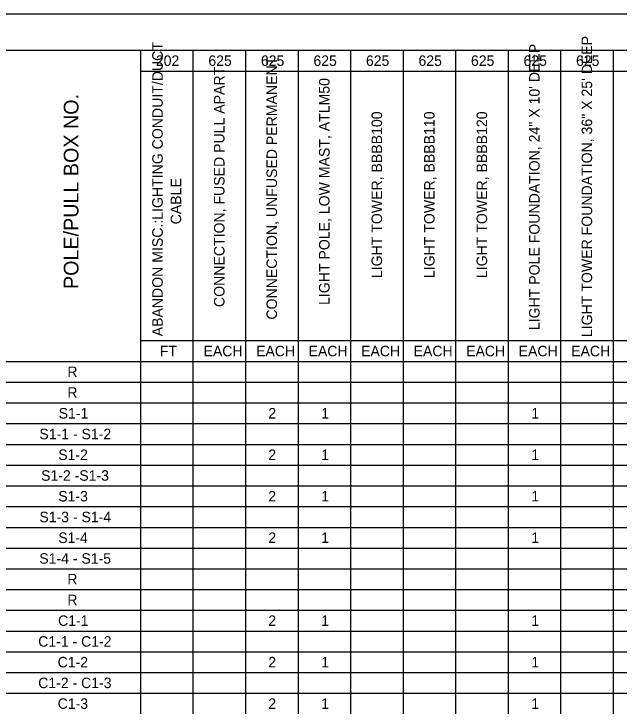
# Model space of a CAD drawing. Extents: x -1022.2 to -988.2, y -965.8 to -943.8.
# Drawn here: x -1013.68 to -1005.35, y -953.43 to -943.79 of the extents above; entities that cross this region are included whole.
import ezdxf

# ---------------------------------------------------------------- set-up
doc = ezdxf.new("R2010")
doc.units = 0
for name, color, linetype in [('Default', 7, 'Continuous'), ('SH_Border', 7, 'Continuous'), ('SH_Cut_Line', 7, 'Continuous')]:
    doc.layers.add(name, color=color, linetype=linetype)

msp = doc.modelspace()

# ---------------------------------------------------------------- linework, layer by layer
at = {"layer": 'Default'}
for p, q in [((-1016.8167, -944.2862), (-1009.047, -944.2862)), ((-1011.9419, -944.2862), (-1011.9419, -944.5719)), ((-1011.2181, -944.2862), (-1011.2181, -944.5719)), ((-1010.4944, -944.2862), (-1010.4944, -944.5719)), ((-1009.7707, -944.2862), (-1009.7707, -944.5719)), ((-1009.047, -944.2862), (-1008.3233, -944.2862)), ((-1009.047, -944.2862), (-1009.047, -944.5719)), ((-1008.3233, -944.2862), (-1007.5995, -944.2862)), ((-1008.3233, -944.2862), (-1008.3233, -944.5719)), ((-1007.5995, -944.2862), (-1006.8758, -944.2862)), ((-1007.5995, -944.2862), (-1007.5995, -944.5719)), ((-1006.8758, -944.2862), (-1005.4284, -944.2862)), ((-1006.8758, -944.2862), (-1006.8758, -944.5719)), ((-1006.1521, -944.2862), (-1006.1521, -944.5719)), ((-1005.4284, -944.2862), (-998.9149, -944.2862)), ((-1005.4284, -944.2862), (-1005.4284, -944.5719)), ((-1011.9419, -944.5719), (-1009.047, -944.5719)), ((-1011.9419, -944.5719), (-1011.9419, -944.8577)), ((-1011.2181, -944.5719), (-1011.2181, -944.8577)), ((-1010.4944, -944.5719), (-1010.4944, -944.8577)), ((-1009.7707, -944.5719), (-1009.7707, -944.8577)), ((-1009.047, -944.5719), (-1008.3233, -944.5719)), ((-1009.047, -944.5719), (-1009.047, -944.8577)), ((-1008.3233, -944.5719), (-1007.5995, -944.5719)), ((-1008.3233, -944.5719), (-1008.3233, -944.8577)), ((-1007.5995, -944.5719), (-1006.8758, -944.5719)), ((-1007.5995, -944.5719), (-1007.5995, -944.8577)), ((-1006.8758, -944.5719), (-1005.4284, -944.5719)), ((-1006.8758, -944.5719), (-1006.8758, -944.8577)), ((-1006.1521, -944.5719), (-1006.1521, -944.8577)), ((-1005.4284, -944.5719), (-998.9149, -944.5719)), ((-1005.4284, -944.5719), (-1005.4284, -944.8577)), ((-1011.9419, -944.8577), (-1011.9419, -945.1434)), ((-1011.2181, -944.8577), (-1011.2181, -945.1434)), ((-1010.4944, -944.8577), (-1010.4944, -945.1434)), ((-1009.7707, -944.8577), (-1009.7707, -945.1434)), ((-1009.047, -944.8577), (-1009.047, -945.1434)), ((-1008.3233, -944.8577), (-1008.3233, -945.1434)), ((-1007.5995, -944.8577), (-1007.5995, -945.1434)), ((-1006.8758, -944.8577), (-1006.8758, -945.1434)), ((-1006.1521, -944.8577), (-1006.1521, -945.1434)), ((-1005.4284, -944.8577), (-1005.4284, -945.1434)), ((-1011.9419, -945.1434), (-1011.9419, -945.4292)), ((-1011.2181, -945.1434), (-1011.2181, -945.4292)), ((-1010.4944, -945.1434), (-1010.4944, -945.4292)), ((-1009.7707, -945.1434), (-1009.7707, -945.4292)), ((-1009.047, -945.1434), (-1009.047, -945.4292)), ((-1008.3233, -945.1434), (-1008.3233, -945.4292)), ((-1007.5995, -945.1434), (-1007.5995, -945.4292)), ((-1006.8758, -945.1434), (-1006.8758, -945.4292)), ((-1006.1521, -945.1434), (-1006.1521, -945.4292)), ((-1005.4284, -945.1434), (-1005.4284, -945.4292)), ((-1011.9419, -945.4292), (-1011.9419, -945.7149)), ((-1011.2181, -945.4292), (-1011.2181, -945.7149)), ((-1010.4944, -945.4292), (-1010.4944, -945.7149)), ((-1009.7707, -945.4292), (-1009.7707, -945.7149)), ((-1009.047, -945.4292), (-1009.047, -945.7149)), ((-1008.3233, -945.4292), (-1008.3233, -945.7149)), ((-1007.5995, -945.4292), (-1007.5995, -945.7149)), ((-1006.8758, -945.4292), (-1006.8758, -945.7149)), ((-1006.1521, -945.4292), (-1006.1521, -945.7149)), ((-1005.4284, -945.4292), (-1005.4284, -945.7149)), ((-1011.9419, -945.7149), (-1011.9419, -946.0006)), ((-1011.2181, -945.7149), (-1011.2181, -946.0006)), ((-1010.4944, -945.7149), (-1010.4944, -946.0006)), ((-1009.7707, -945.7149), (-1009.7707, -946.0006)), ((-1009.047, -945.7149), (-1009.047, -946.0006)), ((-1008.3233, -945.7149), (-1008.3233, -946.0006)), ((-1007.5995, -945.7149), (-1007.5995, -946.0006)), ((-1006.8758, -945.7149), (-1006.8758, -946.0006)), ((-1006.1521, -945.7149), (-1006.1521, -946.0006)), ((-1005.4284, -945.7149), (-1005.4284, -946.0006)), ((-1011.9419, -946.0006), (-1011.9419, -946.2864)), ((-1011.2181, -946.0006), (-1011.2181, -946.2864)), ((-1010.4944, -946.0006), (-1010.4944, -946.2864)), ((-1009.7707, -946.0006), (-1009.7707, -946.2864)), ((-1009.047, -946.0006), (-1009.047, -946.2864)), ((-1008.3233, -946.0006), (-1008.3233, -946.2864)), ((-1007.5995, -946.0006), (-1007.5995, -946.2864)), ((-1006.8758, -946.0006), (-1006.8758, -946.2864)), ((-1006.1521, -946.0006), (-1006.1521, -946.2864)), ((-1005.4284, -946.0006), (-1005.4284, -946.2864)), ((-1011.9419, -946.2864), (-1011.9419, -946.8578)), ((-1011.2181, -946.2864), (-1011.2181, -946.8578)), ((-1010.4944, -946.2864), (-1010.4944, -946.8578)), ((-1009.7707, -946.2864), (-1009.7707, -946.8578)), ((-1009.047, -946.2864), (-1009.047, -946.8578)), ((-1008.3233, -946.2864), (-1008.3233, -946.8578)), ((-1007.5995, -946.2864), (-1007.5995, -946.8578)), ((-1006.8758, -946.2864), (-1006.8758, -946.8578)), ((-1006.1521, -946.2864), (-1006.1521, -946.8578)), ((-1005.4284, -946.2864), (-1005.4284, -946.8578)), ((-1011.9419, -946.8578), (-1011.9419, -947.7151)), ((-1011.2181, -946.8578), (-1011.2181, -947.7151)), ((-1010.4944, -946.8578), (-1010.4944, -947.7151)), ((-1009.7707, -946.8578), (-1009.7707, -947.7151)), ((-1009.047, -946.8578), (-1009.047, -947.7151)), ((-1008.3233, -946.8578), (-1008.3233, -947.7151)), ((-1007.5995, -946.8578), (-1007.5995, -947.7151)), ((-1006.8758, -946.8578), (-1006.8758, -947.7151)), ((-1006.1521, -946.8578), (-1006.1521, -947.7151)), ((-1005.4284, -946.8578), (-1005.4284, -947.7151)), ((-1011.9419, -947.7151), (-1011.9419, -948.0008)), ((-1011.2181, -947.7151), (-1011.2181, -948.0008)), ((-1010.4944, -947.7151), (-1010.4944, -948.0008)), ((-1009.7707, -947.7151), (-1009.7707, -948.0008)), ((-1009.047, -947.7151), (-1009.047, -948.0008)), ((-1008.3233, -947.7151), (-1008.3233, -948.0008)), ((-1007.5995, -947.7151), (-1007.5995, -948.0008)), ((-1006.8758, -947.7151), (-1006.8758, -948.0008)), ((-1006.1521, -947.7151), (-1006.1521, -948.0008)), ((-1005.4284, -947.7151), (-1005.4284, -948.0008)), ((-1011.9419, -948.0008), (-1011.9419, -948.5723)), ((-1011.2181, -948.0008), (-1011.2181, -948.5723)), ((-1010.4944, -948.0008), (-1010.4944, -948.5723)), ((-1009.7707, -948.0008), (-1009.7707, -948.5723)), ((-1009.047, -948.0008), (-1009.047, -948.5723)), ((-1008.3233, -948.0008), (-1008.3233, -948.5723)), ((-1007.5995, -948.0008), (-1007.5995, -948.5723)), ((-1006.8758, -948.0008), (-1006.8758, -948.5723)), ((-1006.1521, -948.0008), (-1006.1521, -948.5723)), ((-1005.4284, -948.0008), (-1005.4284, -948.5723)), ((-1011.9419, -948.2865), (-1009.047, -948.2865)), ((-1009.047, -948.2865), (-1008.3233, -948.2865)), ((-1008.3233, -948.2865), (-1007.5995, -948.2865)), ((-1007.5995, -948.2865), (-1006.8758, -948.2865)), ((-1006.8758, -948.2865), (-1005.4284, -948.2865)), ((-1005.4284, -948.2865), (-998.9149, -948.2865)), ((-1016.8167, -948.5723), (-1009.047, -948.5723)), ((-1011.9419, -948.5723), (-1011.9419, -948.858)), ((-1011.2181, -948.5723), (-1011.2181, -948.858)), ((-1010.4944, -948.5723), (-1010.4944, -948.858)), ((-1009.7707, -948.5723), (-1009.7707, -948.858)), ((-1009.047, -948.5723), (-1008.3233, -948.5723)), ((-1009.047, -948.5723), (-1009.047, -948.858)), ((-1008.3233, -948.5723), (-1007.5995, -948.5723)), ((-1008.3233, -948.5723), (-1008.3233, -948.858)), ((-1007.5995, -948.5723), (-1006.8758, -948.5723)), ((-1007.5995, -948.5723), (-1007.5995, -948.858)), ((-1006.8758, -948.5723), (-1005.4284, -948.5723)), ((-1006.8758, -948.5723), (-1006.8758, -948.858)), ((-1006.1521, -948.5723), (-1006.1521, -948.858)), ((-1005.4284, -948.5723), (-998.9149, -948.5723)), ((-1005.4284, -948.5723), (-1005.4284, -948.858)), ((-1016.8167, -948.858), (-1009.047, -948.858)), ((-1011.9419, -948.858), (-1011.9419, -950.001)), ((-1011.2181, -948.858), (-1011.2181, -950.001)), ((-1010.4944, -948.858), (-1010.4944, -950.001)), ((-1009.7707, -948.858), (-1009.7707, -950.001)), ((-1009.047, -948.858), (-1008.3233, -948.858)), ((-1009.047, -948.858), (-1009.047, -950.001)), ((-1008.3233, -948.858), (-1007.5995, -948.858)), ((-1008.3233, -948.858), (-1008.3233, -950.001)), ((-1007.5995, -948.858), (-1006.8758, -948.858)), ((-1007.5995, -948.858), (-1007.5995, -950.001)), ((-1006.8758, -948.858), (-1005.4284, -948.858)), ((-1006.8758, -948.858), (-1006.8758, -950.001)), ((-1006.1521, -948.858), (-1006.1521, -950.001)), ((-1005.4284, -948.858), (-998.9149, -948.858)), ((-1005.4284, -948.858), (-1005.4284, -950.001)), ((-1016.8167, -949.1437), (-1009.047, -949.1437)), ((-1009.047, -949.1437), (-1008.3233, -949.1437)), ((-1008.3233, -949.1437), (-1007.5995, -949.1437)), ((-1007.5995, -949.1437), (-1006.8758, -949.1437)), ((-1006.8758, -949.1437), (-1005.4284, -949.1437)), ((-1005.4284, -949.1437), (-998.9149, -949.1437)), ((-1016.8167, -949.4295), (-1009.047, -949.4295)), ((-1009.047, -949.4295), (-1008.3233, -949.4295)), ((-1008.3233, -949.4295), (-1007.5995, -949.4295)), ((-1007.5995, -949.4295), (-1006.8758, -949.4295)), ((-1006.8758, -949.4295), (-1005.4284, -949.4295)), ((-1005.4284, -949.4295), (-998.9149, -949.4295)), ((-1016.8167, -949.7152), (-1009.047, -949.7152)), ((-1009.047, -949.7152), (-1008.3233, -949.7152)), ((-1008.3233, -949.7152), (-1007.5995, -949.7152)), ((-1007.5995, -949.7152), (-1006.8758, -949.7152)), ((-1006.8758, -949.7152), (-1005.4284, -949.7152)), ((-1005.4284, -949.7152), (-998.9149, -949.7152)), ((-1016.8167, -950.001), (-1009.047, -950.001)), ((-1011.9419, -950.001), (-1011.9419, -950.2867)), ((-1011.2181, -950.001), (-1011.2181, -950.2867)), ((-1010.4944, -950.001), (-1010.4944, -950.2867)), ((-1009.7707, -950.001), (-1009.7707, -950.2867)), ((-1009.047, -950.001), (-1008.3233, -950.001)), ((-1009.047, -950.001), (-1009.047, -950.2867)), ((-1008.3233, -950.001), (-1007.5995, -950.001)), ((-1008.3233, -950.001), (-1008.3233, -950.2867)), ((-1007.5995, -950.001), (-1006.8758, -950.001)), ((-1007.5995, -950.001), (-1007.5995, -950.2867)), ((-1006.8758, -950.001), (-1005.4284, -950.001)), ((-1006.8758, -950.001), (-1006.8758, -950.2867)), ((-1006.1521, -950.001), (-1006.1521, -950.2867)), ((-1005.4284, -950.001), (-998.9149, -950.001)), ((-1005.4284, -950.001), (-1005.4284, -950.2867)), ((-1016.8167, -950.2867), (-1009.047, -950.2867)), ((-1011.9419, -950.2867), (-1011.9419, -950.8582)), ((-1011.2181, -950.2867), (-1011.2181, -950.8582)), ((-1010.4944, -950.2867), (-1010.4944, -950.8582)), ((-1009.7707, -950.2867), (-1009.7707, -950.8582)), ((-1009.047, -950.2867), (-1008.3233, -950.2867)), ((-1009.047, -950.2867), (-1009.047, -950.8582)), ((-1008.3233, -950.2867), (-1007.5995, -950.2867)), ((-1008.3233, -950.2867), (-1008.3233, -950.8582)), ((-1007.5995, -950.2867), (-1006.8758, -950.2867)), ((-1007.5995, -950.2867), (-1007.5995, -950.8582)), ((-1006.8758, -950.2867), (-1005.4284, -950.2867)), ((-1006.8758, -950.2867), (-1006.8758, -950.8582)), ((-1006.1521, -950.2867), (-1006.1521, -950.8582)), ((-1005.4284, -950.2867), (-998.9149, -950.2867)), ((-1005.4284, -950.2867), (-1005.4284, -950.8582)), ((-1016.8167, -950.5724), (-1009.047, -950.5724)), ((-1009.047, -950.5724), (-1008.3233, -950.5724)), ((-1008.3233, -950.5724), (-1007.5995, -950.5724)), ((-1007.5995, -950.5724), (-1006.8758, -950.5724)), ((-1006.8758, -950.5724), (-1005.4284, -950.5724)), ((-1005.4284, -950.5724), (-998.9149, -950.5724)), ((-1016.8167, -950.8582), (-1009.047, -950.8582)), ((-1011.9419, -950.8582), (-1011.9419, -951.4296)), ((-1011.2181, -950.8582), (-1011.2181, -951.4296)), ((-1010.4944, -950.8582), (-1010.4944, -951.4296)), ((-1009.7707, -950.8582), (-1009.7707, -951.4296)), ((-1009.047, -950.8582), (-1008.3233, -950.8582)), ((-1009.047, -950.8582), (-1009.047, -951.4296)), ((-1008.3233, -950.8582), (-1007.5995, -950.8582)), ((-1008.3233, -950.8582), (-1008.3233, -951.4296)), ((-1007.5995, -950.8582), (-1006.8758, -950.8582)), ((-1007.5995, -950.8582), (-1007.5995, -951.4296)), ((-1006.8758, -950.8582), (-1005.4284, -950.8582)), ((-1006.8758, -950.8582), (-1006.8758, -951.4296)), ((-1006.1521, -950.8582), (-1006.1521, -951.4296)), ((-1005.4284, -950.8582), (-998.9149, -950.8582)), ((-1005.4284, -950.8582), (-1005.4284, -951.4296)), ((-1016.8167, -951.1439), (-1009.047, -951.1439)), ((-1009.047, -951.1439), (-1008.3233, -951.1439)), ((-1008.3233, -951.1439), (-1007.5995, -951.1439)), ((-1007.5995, -951.1439), (-1006.8758, -951.1439)), ((-1006.8758, -951.1439), (-1005.4284, -951.1439)), ((-1005.4284, -951.1439), (-998.9149, -951.1439)), ((-1016.8167, -951.4296), (-1009.047, -951.4296)), ((-1011.9419, -951.4296), (-1011.9419, -951.7154)), ((-1011.2181, -951.4296), (-1011.2181, -951.7154)), ((-1010.4944, -951.4296), (-1010.4944, -951.7154)), ((-1009.7707, -951.4296), (-1009.7707, -951.7154)), ((-1009.047, -951.4296), (-1008.3233, -951.4296)), ((-1009.047, -951.4296), (-1009.047, -951.7154)), ((-1008.3233, -951.4296), (-1007.5995, -951.4296)), ((-1008.3233, -951.4296), (-1008.3233, -951.7154)), ((-1007.5995, -951.4296), (-1006.8758, -951.4296)), ((-1007.5995, -951.4296), (-1007.5995, -951.7154)), ((-1006.8758, -951.4296), (-1005.4284, -951.4296)), ((-1006.8758, -951.4296), (-1006.8758, -951.7154)), ((-1006.1521, -951.4296), (-1006.1521, -951.7154)), ((-1005.4284, -951.4296), (-998.9149, -951.4296)), ((-1005.4284, -951.4296), (-1005.4284, -951.7154)), ((-1016.8167, -951.7154), (-1009.047, -951.7154)), ((-1011.9419, -951.7154), (-1011.9419, -952.2869)), ((-1011.2181, -951.7154), (-1011.2181, -952.2869)), ((-1010.4944, -951.7154), (-1010.4944, -952.2869)), ((-1009.7707, -951.7154), (-1009.7707, -952.2869)), ((-1009.047, -951.7154), (-1008.3233, -951.7154)), ((-1009.047, -951.7154), (-1009.047, -952.2869)), ((-1008.3233, -951.7154), (-1007.5995, -951.7154)), ((-1008.3233, -951.7154), (-1008.3233, -952.2869)), ((-1007.5995, -951.7154), (-1006.8758, -951.7154)), ((-1007.5995, -951.7154), (-1007.5995, -952.2869)), ((-1006.8758, -951.7154), (-1005.4284, -951.7154)), ((-1006.8758, -951.7154), (-1006.8758, -952.2869)), ((-1006.1521, -951.7154), (-1006.1521, -952.2869)), ((-1005.4284, -951.7154), (-998.9149, -951.7154)), ((-1005.4284, -951.7154), (-1005.4284, -952.2869)), ((-1016.8167, -952.0011), (-1009.047, -952.0011)), ((-1009.047, -952.0011), (-1008.3233, -952.0011)), ((-1008.3233, -952.0011), (-1007.5995, -952.0011)), ((-1007.5995, -952.0011), (-1006.8758, -952.0011)), ((-1006.8758, -952.0011), (-1005.4284, -952.0011)), ((-1005.4284, -952.0011), (-998.9149, -952.0011)), ((-1016.8167, -952.2869), (-1009.047, -952.2869)), ((-1011.9419, -952.2869), (-1011.9419, -952.5726)), ((-1011.2181, -952.2869), (-1011.2181, -952.5726)), ((-1010.4944, -952.2869), (-1010.4944, -952.5726)), ((-1009.7707, -952.2869), (-1009.7707, -952.5726)), ((-1009.047, -952.2869), (-1008.3233, -952.2869)), ((-1009.047, -952.2869), (-1009.047, -952.5726)), ((-1008.3233, -952.2869), (-1007.5995, -952.2869)), ((-1008.3233, -952.2869), (-1008.3233, -952.5726)), ((-1007.5995, -952.2869), (-1006.8758, -952.2869)), ((-1007.5995, -952.2869), (-1007.5995, -952.5726)), ((-1006.8758, -952.2869), (-1005.4284, -952.2869)), ((-1006.8758, -952.2869), (-1006.8758, -952.5726)), ((-1006.1521, -952.2869), (-1006.1521, -952.5726)), ((-1005.4284, -952.2869), (-998.9149, -952.2869)), ((-1005.4284, -952.2869), (-1005.4284, -952.5726)), ((-1016.8167, -952.5726), (-1009.047, -952.5726)), ((-1011.9419, -952.5726), (-1011.9419, -953.4298)), ((-1011.2181, -952.5726), (-1011.2181, -953.4298)), ((-1010.4944, -952.5726), (-1010.4944, -953.4298)), ((-1009.7707, -952.5726), (-1009.7707, -953.4298)), ((-1009.047, -952.5726), (-1008.3233, -952.5726)), ((-1009.047, -952.5726), (-1009.047, -953.4298)), ((-1008.3233, -952.5726), (-1007.5995, -952.5726)), ((-1008.3233, -952.5726), (-1008.3233, -953.4298)), ((-1007.5995, -952.5726), (-1006.8758, -952.5726)), ((-1007.5995, -952.5726), (-1007.5995, -953.4298)), ((-1006.8758, -952.5726), (-1005.4284, -952.5726)), ((-1006.8758, -952.5726), (-1006.8758, -953.4298)), ((-1006.1521, -952.5726), (-1006.1521, -953.4298)), ((-1005.4284, -952.5726), (-998.9149, -952.5726)), ((-1005.4284, -952.5726), (-1005.4284, -953.4298)), ((-1016.8167, -952.8583), (-1009.047, -952.8583)), ((-1009.047, -952.8583), (-1008.3233, -952.8583)), ((-1008.3233, -952.8583), (-1007.5995, -952.8583)), ((-1007.5995, -952.8583), (-1006.8758, -952.8583)), ((-1006.8758, -952.8583), (-1005.4284, -952.8583)), ((-1005.4284, -952.8583), (-998.9149, -952.8583)), ((-1016.8167, -953.1441), (-1009.047, -953.1441)), ((-1009.047, -953.1441), (-1008.3233, -953.1441)), ((-1008.3233, -953.1441), (-1007.5995, -953.1441)), ((-1007.5995, -953.1441), (-1006.8758, -953.1441)), ((-1006.8758, -953.1441), (-1005.4284, -953.1441)), ((-1005.4284, -953.1441), (-998.9149, -953.1441))]:
    msp.add_line(p, q, dxfattribs=at)
at = {"layer": 'SH_Border'}
msp.add_lwpolyline([(-1020.7494, -944.2862), (-988.7494, -944.2862), (-988.7494, -965.2862), (-1020.7494, -965.2862)], close=True, dxfattribs=at)
at = {"layer": 'SH_Cut_Line'}
msp.add_lwpolyline([(-1022.2494, -965.7862), (-988.2494, -965.7862), (-988.2494, -943.7862), (-1022.2494, -943.7862)], close=True, dxfattribs=at)

# ---------------------------------------------------------------- texts
at = {"layer": 'Default'}
for s, height, p in [('LIGHT TOWER FOUNDATION, 36" X 25\' DEEP', 0.145085, (-1005.7177, -948.2371)), ('ABANDON MISC.:LIGHTING CONDUIT/DUCT ', 0.145085, (-1011.6344, -948.227)), ('LIGHT POLE FOUNDATION, 24" X 10\' DEEP', 0.145085, (-1006.4414, -948.1416)), ('CONNECTION, UNFUSED PERMANENT', 0.145085, (-1010.06, -947.9963)), ('CONNECTION, FUSED PULL APART', 0.145085, (-1010.7837, -947.8231)), ('LIGHT POLE, LOW MAST, ATLM50', 0.145085, (-1009.3363, -947.7948)), ('POLE/PULL BOX NO.', 0.203119, (-1012.7961, -947.5749)), ('LIGHT TOWER, BBBB100', 0.145085, (-1008.6126, -947.4247)), ('LIGHT TOWER, BBBB110', 0.145085, (-1007.8889, -947.4247)), ('LIGHT TOWER, BBBB120', 0.145085, (-1007.1651, -947.4247)), ('CABLE', 0.14508, (-1011.3805, -946.6839))]:
    msp.add_text(s, height=height, rotation=90, dxfattribs=at).set_placement(p)
for s, height, p in [('202', 0.14457, (-1011.7298, -944.5014)), ('625', 0.14457, (-1011.0059, -944.5014)), ('625', 0.14457, (-1010.2821, -944.5014)), ('625', 0.14457, (-1009.5584, -944.5014)), ('625', 0.14457, (-1008.8347, -944.5014)), ('625', 0.14457, (-1008.111, -944.5014)), ('625', 0.14457, (-1007.3873, -944.5014)), ('625', 0.14457, (-1006.6636, -944.5014)), ('625', 0.14457, (-1005.9398, -944.5014)), ('EACH', 0.14457, (-1011.0723, -948.5017)), ('EACH', 0.14457, (-1010.3486, -948.5017)), ('EACH', 0.14457, (-1009.6249, -948.5017)), ('EACH', 0.14457, (-1008.9012, -948.5017)), ('EACH', 0.14457, (-1008.1774, -948.5017)), ('EACH', 0.14457, (-1007.4537, -948.5017)), ('EACH', 0.14457, (-1006.73, -948.5017)), ('EACH', 0.14457, (-1006.0063, -948.5017)), ('FT', 0.14457, (-1011.6762, -948.5017)), ('R', 0.1446, (-1012.9491, -948.7874)), ('R', 0.1446, (-1012.9491, -949.0732)), ('S1-1', 0.14457, (-1013.0691, -949.3589)), ('2', 0.1446, (-1010.1803, -949.3589)), ('1', 0.1446, (-1009.4508, -949.3589)), ('1', 0.1446, (-1006.556, -949.3589)), ('S1-1 - S1-2', 0.14457, (-1013.3343, -949.6446)), ('S1-2', 0.14457, (-1013.0748, -949.9304)), ('2', 0.1446, (-1010.1803, -949.9304)), ('1', 0.1446, (-1009.4508, -949.9304)), ('1', 0.1446, (-1006.556, -949.9304)), ('S1-2 -S1-3', 0.14457, (-1013.3108, -950.2161)), ('S1-3', 0.14457, (-1013.0745, -950.5018)), ('2', 0.1446, (-1010.1803, -950.5018)), ('1', 0.1446, (-1009.4508, -950.5018)), ('1', 0.1446, (-1006.556, -950.5018)), ('S1-3 - S1-4', 0.14457, (-1013.3344, -950.7876)), ('S1-4', 0.14457, (-1013.0749, -951.0733)), ('2', 0.1446, (-1010.1803, -951.0733)), ('1', 0.1446, (-1009.4508, -951.0733)), ('1', 0.1446, (-1006.556, -951.0733)), ('S1-4 - S1-5', 0.14457, (-1013.3358, -951.3591)), ('R', 0.1446, (-1012.9491, -951.6448)), ('R', 0.1446, (-1012.9491, -951.9305)), ('C1-1', 0.14457, (-1013.0773, -952.2163)), ('2', 0.1446, (-1010.1803, -952.2163)), ('1', 0.1446, (-1009.4508, -952.2163)), ('1', 0.1446, (-1006.556, -952.2163)), ('C1-1 - C1-2', 0.14457, (-1013.3507, -952.502)), ('C1-2', 0.14457, (-1013.083, -952.7877)), ('2', 0.1446, (-1010.1803, -952.7877)), ('1', 0.1446, (-1009.4508, -952.7877)), ('1', 0.1446, (-1006.556, -952.7877)), ('C1-2 - C1-3', 0.14457, (-1013.3504, -953.0735)), ('C1-3', 0.14457, (-1013.0827, -953.3592)), ('2', 0.1446, (-1010.1803, -953.3592)), ('1', 0.1446, (-1009.4508, -953.3592)), ('1', 0.1446, (-1006.556, -953.3592))]:
    msp.add_text(s, height=height, dxfattribs=at).set_placement(p)

doc.saveas('drawing.dxf')
